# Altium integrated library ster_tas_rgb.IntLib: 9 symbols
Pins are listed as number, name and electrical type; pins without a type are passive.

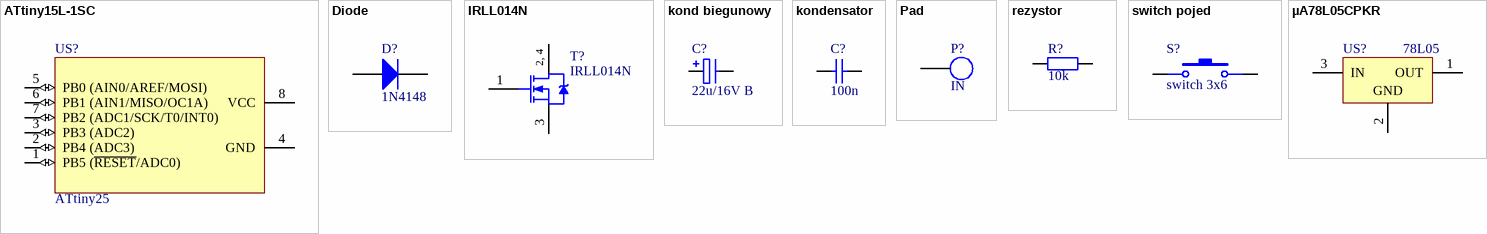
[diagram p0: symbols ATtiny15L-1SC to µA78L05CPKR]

## ATtiny15L-1SC
designator US?, comment ATtiny25
8-Bit AVR Microcontroller with 1K Byte of Flash Memory
footprint 8S2_N (SOP, 8-Leads, Body 5.3x5.3mm, Pitch 1.27mm, IPC Medium Density)
footprint 8S2_L (SOP, 8-Leads, Body 5.3x5.3mm, Pitch 1.27mm, IPC High Density)
footprint 8S2_M (SOP, 8-Leads, Body 5.3x5.3mm, Pitch 1.27mm, IPC Low Density)
3D model 8S2 (8-Pin Small Outline Package 1.27 mm Pitch)
pins: 1 PB5 (~{RESET}/ADC0) (io), 2 PB4 (ADC3) (io), 3 PB3 (ADC2) (io), 4 GND (power), 5 PB0 (AIN0/AREF/MOSI) (io), 6 PB1 (AIN1/MISO/OC1A) (io), 7 PB2 (ADC1/SCK/T0/INT0) (io), 8 VCC (power)

## Diode
designator D?, comment 1N4148
Default Diode
footprint dioda 10mm
footprint dioda 17,5mm
footprint dioda 7,5mm
footprint dioda MINIMELF (SMT LED; 2 Flat Leads)
pins: 1 A, 2 K

## IRLL014N
designator T?
HEXFET Power MOSFET; Note: Pin 2 is electrically connected to pin 4.
footprint SOT-223 (SOT-223/SC-73; 4 Leads; Body 6.7 x 7.3 mm, inc. leads (LxW max))
simulation model IRLL014N (SUBCKT)
pins: 1 G, 2 D, 3 S, 4 D

## kond biegunowy
designator C?, comment 22u/16V B
Polarized Capacitor
footprint Tantal B 3528-1411 (Capacitor, SM Tantalum; Body 3.5 x 2.8 mm (LxW typ))
footprint Tantal C 6032-2412 (Capacitor, SM Tantalum; Body 6.0 x 3.2 mm (LxW typ))
footprint Tantal D 7343-2917 (Capacitor, SM Tantalum; Body 7.3 x 4.3 mm (LxW typ))
footprint 2,5/5mm elektrolit
footprint 3,5/7mm elektrolit
footprint 5/10mm elektrolit
footprint 2,5/7mm elektrolit
footprint 7,5/16mm elektrolit
footprint 5/12,5mm elektrolit
footprint Tantal A 3216-1206 (Capacitor, SM Tantalum; Body 3.2 x 1.6 mm (LxW typ))
footprint A SMD elektrolit
footprint B SMD elektrolit
footprint C SMD elektrolit
footprint D SMD elektrolit
footprint E SMD elektrolit
footprint F SMD elektrolit
pins: 1, 2
1 alternate drawing of the same symbol

## kondensator
designator C?, comment 100n
footprint kond 2,5mm
footprint kond 7,5mm
footprint kond 10mm
footprint MELF-0805 (Metal Electrode Face (MELF) Resistor; Body 2 x 1.4 mm (LxDia))
footprint MELF-1206 (Metal Electrode Face (MELF) Resistor; Body 3.2 x 1.8 mm (LxDia))
footprint kond 15mm
footprint kond 5mm chudy
footprint kond 5mm gruby
footprint kond 5mm sredni
pins: 1, 2

## Pad
designator P?, comment IN
Pad
footprint pad fi 0,8mm
footprint pad fi 1,5mm
footprint pad fi 1mm
footprint pad fi 2mm
footprint pad fi 2,5mm
footprint pad fi 4mm
footprint Pad SMD 2x4mm
pins: 1

## rezystor
designator R?, comment 10k
footprint rez 7,5mm
footprint rez 10mm
footprint rez 12,5mm
footprint rez 15mm
footprint rez 17,5mm
footprint MELF-0805 (Metal Electrode Face (MELF) Resistor; Body 2 x 1.4 mm (LxDia))
footprint MELF-1206 (Metal Electrode Face (MELF) Resistor; Body 3.2 x 1.8 mm (LxDia))
footprint rez_bocznik 20mm
pins: 1, 2

## switch pojed
designator S?, comment switch 3x6
footprint tact switch 3x6
pins: 1, 2

## µA78L05CPKR
designator US?, comment 78L05
Positive-Voltage Regulator; Note: Pin 2 is electrically connected to TAB.
footprint PK03 (SOT-89; Body 4.6 x 4.25 mm, inc. leads (LxW max))
pins: 1 OUT (power), 2 GND (power), 3 IN (power)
